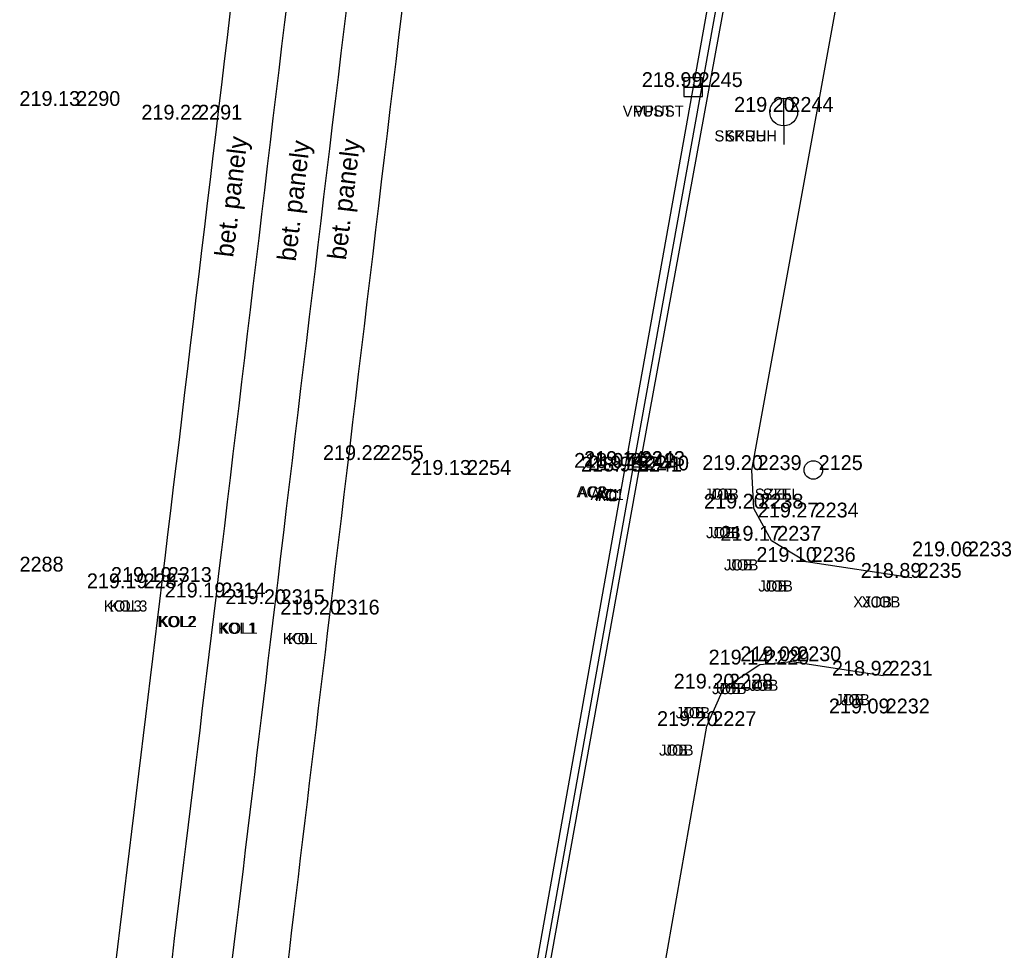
# Model space of a CAD drawing. Extents: x -471047 to -470889, y -1102859 to -1102000.
# Drawn here: x -470942.48 to -470915.72, y -1102237.69 to -1102212.58 of the extents above; entities that cross this region are included whole.
import ezdxf

# ---------------------------------------------------------------- set-up
doc = ezdxf.new("R2010")
doc.units = 0
for name, color, linetype in [('Vrstva 1', 7, 'Continuous'), ('Vrstva 22', 7, 'Continuous'), ('Vrstva 23', 7, 'Continuous'), ('Vrstva 25', 7, 'Continuous'), ('Vrstva 34', 7, 'Continuous'), ('Vrstva 35', 7, 'Continuous'), ('Vrstva 36', 7, 'Continuous'), ('Vrstva 38', 7, 'Continuous'), ('Vrstva 5', 7, 'Continuous'), ('Vrstva 7', 7, 'Continuous'), ('Vrstva 8', 7, 'Continuous')]:
    doc.layers.add(name, color=color, linetype=linetype)

msp = doc.modelspace()

# ---------------------------------------------------------------- linework, layer by layer
at = {"layer": 'Vrstva 1'}
for points in [[(-471040.344, -1102858.385), (-471031.676, -1102846.187), (-471026.357, -1102838.629), (-471023.212, -1102833.975), (-471019.21, -1102827.465), (-471016.861, -1102823.272), (-471013.099, -1102815.912), (-471010.824, -1102810.955), (-471007.329, -1102802.292), (-471005.34, -1102796.515), (-471002.842, -1102787.838), (-471001.3, -1102780.997), (-471000.19, -1102774.713), (-470999.247, -1102768.204), (-470998.794, -1102764.784), (-470997.199, -1102751.812), (-470994.899, -1102732.807), (-470992.551, -1102713.262), (-470990.326, -1102694.887), (-470988.122, -1102676.57), (-470985.812, -1102657.305), (-470983.537, -1102638.407), (-470981.386, -1102620.622), (-470979.843, -1102608.014), (-470976.377, -1102579.253), (-470972.945, -1102550.69), (-470970.475, -1102530.206), (-470967.905, -1102508.801), (-470965.053, -1102485.131), (-470962.734, -1102465.9), (-470960.173, -1102444.812), (-470957.795, -1102425.103), (-470954.965, -1102401.839), (-470953.834, -1102392.574), (-470952.33, -1102379.985), (-470950.744, -1102366.853), (-470948.978, -1102352.106), (-470947.037, -1102335.844), (-470944.949, -1102318.462), (-470944.013, -1102310.745), (-470942.39, -1102297.267), (-470939.519, -1102273.45), (-470937.593, -1102257.43), (-470936.064, -1102244.81), (-470934.114, -1102228.634), (-470931.621, -1102207.856), (-470929.536, -1102190.857), (-470926.572, -1102166.31), (-470924.91, -1102152.663), (-470923.413, -1102140.333), (-470921.923, -1102127.669), (-470921.155, -1102120.084), (-470920.446, -1102109.574), (-470919.912, -1102099.137), (-470919.63, -1102088.981), (-470919.523, -1102081.193), (-470919.563, -1102070.395), (-470919.714, -1102064.236), (-470920.134, -1102054.704), (-470920.462, -1102047.615), (-470920.599, -1102044.52), (-470920.743, -1102041.873), (-470921.125, -1102034.455), (-470921.774, -1102030.337), (-470922.418, -1102027.787), (-470923.734, -1102023.93), (-470924.872, -1102021.434), (-470926.752, -1102018.182), (-470927.953, -1102016.45), (-470929.616, -1102014.424), (-470932.252, -1102011.756), (-470935.111, -1102009.425), (-470938.391, -1102007.371), (-470942.651, -1102005.401)], [(-471041.328, -1102857.18), (-471032.144, -1102844.242), (-471027.583, -1102837.763), (-471024.388, -1102833.028), (-471020.451, -1102826.6), (-471018.089, -1102822.378), (-471014.542, -1102815.445), (-471012.233, -1102810.418), (-471009.247, -1102803.108), (-471006.795, -1102796.098), (-471004.315, -1102787.532), (-471002.782, -1102780.723), (-471001.674, -1102774.458), (-471000.75, -1102768.095), (-471000.28, -1102764.601), (-470998.692, -1102751.741), (-470996.378, -1102732.635), (-470994.028, -1102713.058), (-470991.808, -1102694.749), (-470989.616, -1102676.447), (-470987.284, -1102657.013), (-470985.031, -1102638.272), (-470982.87, -1102620.431), (-470981.334, -1102607.933), (-470977.881, -1102579.263), (-470974.429, -1102550.492), (-470971.964, -1102530.054), (-470969.391, -1102508.607), (-470966.54, -1102484.984), (-470964.231, -1102465.853), (-470961.679, -1102444.752), (-470959.304, -1102425.078), (-470956.455, -1102401.634), (-470955.339, -1102392.489), (-470953.812, -1102379.71), (-470952.249, -1102366.808), (-470950.479, -1102352.023), (-470948.536, -1102335.868), (-470946.426, -1102318.233), (-470945.493, -1102310.531), (-470943.864, -1102297.013), (-470940.984, -1102273.071), (-470939.078, -1102257.195), (-470937.559, -1102244.684), (-470935.592, -1102228.353), (-470933.101, -1102207.653), (-470931.011, -1102190.57), (-470928.046, -1102166.021), (-470926.409, -1102152.578), (-470924.898, -1102140.121), (-470923.427, -1102127.544), (-470922.647, -1102119.826), (-470921.919, -1102109.229), (-470921.42, -1102099.134), (-470921.127, -1102089.016), (-470921.023, -1102081.453), (-470921.061, -1102070.468), (-470921.209, -1102064.314), (-470921.666, -1102053.966), (-470922.156, -1102043.345), (-470922.299, -1102039.934), (-470922.637, -1102034.36), (-470923.091, -1102031.241), (-470923.847, -1102028.247), (-470925.083, -1102024.594), (-470926.222, -1102022.086), (-470928.04, -1102018.943), (-470929.138, -1102017.357), (-470930.929, -1102015.175), (-470933.062, -1102013.049), (-470936.379, -1102010.368), (-470939.169, -1102008.662), (-470942.899, -1102006.906), (-470945.661, -1102005.908)], [(-471043.557, -1102855.955), (-471035.129, -1102844.026), (-471029.872, -1102836.499), (-471026.577, -1102831.578), (-471022.675, -1102825.415), (-471020.123, -1102821.053), (-471016.667, -1102814.59), (-471014.208, -1102809.45), (-471011.177, -1102802.451), (-471008.55, -1102795.333), (-471006.082, -1102787.209), (-471004.464, -1102780.376), (-471003.265, -1102774.167), (-471002.327, -1102767.948), (-471001.636, -1102762.527), (-471000.297, -1102751.605), (-470997.959, -1102732.524), (-470995.602, -1102712.802), (-470993.412, -1102694.623), (-470991.21, -1102676.17), (-470988.891, -1102656.857), (-470986.625, -1102638.083), (-470984.455, -1102620.195), (-470982.936, -1102607.733), (-470979.497, -1102579.223), (-470976.023, -1102550.279), (-470973.554, -1102529.822), (-470970.991, -1102508.497), (-470968.146, -1102484.787), (-470965.835, -1102465.72), (-470963.284, -1102444.529), (-470960.91, -1102424.942), (-470958.043, -1102401.343), (-470956.946, -1102392.356), (-470955.396, -1102379.408), (-470953.851, -1102366.636), (-470952.049, -1102351.733), (-470950.124, -1102335.611), (-470948.034, -1102318.083), (-470947.094, -1102310.328), (-470945.421, -1102296.51), (-470942.58, -1102272.848), (-470940.675, -1102256.948), (-470939.176, -1102244.526), (-470937.187, -1102228.174), (-470934.708, -1102207.467), (-470932.621, -1102190.433), (-470929.634, -1102165.778), (-470928.004, -1102152.415), (-470926.45, -1102139.595), (-470925.003, -1102127.418), (-470924.249, -1102119.695), (-470923.515, -1102109.093), (-470923.018, -1102099.069), (-470922.711, -1102088.911), (-470922.643, -1102081.356), (-470922.797, -1102070.414), (-470923.018, -1102064.454), (-470923.52, -1102053.203), (-470923.823, -1102047.529), (-470924.123, -1102041.506), (-470924.462, -1102037.486), (-470924.934, -1102031.904), (-470925.664, -1102028.672), (-470926.771, -1102025.506), (-470927.959, -1102022.914), (-470929.674, -1102020.028), (-470930.76, -1102018.498), (-470932.447, -1102016.478), (-470935.215, -1102013.816), (-470937.644, -1102011.98), (-470940.381, -1102010.371), (-470943.968, -1102008.669), (-470947.145, -1102007.524), (-470950.874, -1102006.74)], [(-471044.756, -1102855.056), (-471036.376, -1102843.177), (-471031.167, -1102835.741), (-471027.859, -1102830.8), (-471023.934, -1102824.593), (-471021.43, -1102820.312), (-471018.011, -1102813.91), (-471015.536, -1102808.75), (-471012.578, -1102801.897), (-471009.95, -1102794.77), (-471007.561, -1102786.914), (-471005.936, -1102780.074), (-471004.727, -1102773.818), (-471003.828, -1102767.827), (-471003.121, -1102762.345), (-471001.787, -1102751.467), (-470999.446, -1102732.348), (-470997.073, -1102712.539), (-470994.902, -1102694.521), (-470992.696, -1102676.023), (-470990.376, -1102656.68), (-470988.131, -1102638.071), (-470985.947, -1102620.018), (-470984.417, -1102607.512), (-470980.993, -1102579.08), (-470977.514, -1102550.137), (-470975.048, -1102529.649), (-470972.488, -1102508.37), (-470969.618, -1102484.508), (-470967.34, -1102465.669), (-470964.767, -1102444.39), (-470962.402, -1102424.781), (-470959.534, -1102401.193), (-470958.432, -1102392.151), (-470956.883, -1102379.208), (-470955.335, -1102366.424), (-470953.535, -1102351.506), (-470951.606, -1102335.399), (-470949.519, -1102317.94), (-470948.575, -1102310.159), (-470946.889, -1102296.144), (-470944.056, -1102272.618), (-470942.139, -1102256.659), (-470940.657, -1102244.341), (-470938.638, -1102227.749), (-470936.19, -1102207.298), (-470934.102, -1102190.255), (-470931.124, -1102165.639), (-470929.492, -1102152.254), (-470927.915, -1102139.252), (-470926.46, -1102127.103), (-470925.74, -1102119.604), (-470925.012, -1102108.913), (-470924.523, -1102099.054), (-470924.217, -1102088.866), (-470924.148, -1102081.334), (-470924.301, -1102070.391), (-470924.518, -1102064.43), (-470924.97, -1102054.435), (-470925.588, -1102041.569), (-470925.963, -1102035.313), (-470926.405, -1102032.225), (-470927.078, -1102029.198), (-470928.123, -1102026.148), (-470929.318, -1102023.558), (-470930.84, -1102020.97), (-470931.868, -1102019.515), (-470933.443, -1102017.605), (-470936.26, -1102014.885), (-470938.429, -1102013.255), (-470941.213, -1102011.639), (-470944.847, -1102009.927), (-470947.723, -1102008.912), (-470951.444, -1102008.161), (-470954.511, -1102007.931), (-470957.895, -1102008.041)]]:
    msp.add_spline(points, degree=3, dxfattribs=at)
at = {"layer": 'Vrstva 23'}
msp.add_circle((-470921.065, -1102224.727), 0.25, dxfattribs=at)
at = {"layer": 'Vrstva 25'}
for p, q in [((-470924.56, -1102214.144), (-470924.56, -1102214.644)), ((-470924.06, -1102214.144), (-470924.56, -1102214.144)), ((-470924.06, -1102214.644), (-470924.06, -1102214.144)), ((-470924.56, -1102214.394), (-470924.06, -1102214.394)), ((-470924.56, -1102214.644), (-470924.06, -1102214.644)), ((-470921.864, -1102215.439), (-470921.864, -1102214.689)), ((-470921.864, -1102215.439), (-470921.864, -1102215.939))]:
    msp.add_line(p, q, dxfattribs=at)
msp.add_circle((-470921.864, -1102215.064), 0.375, dxfattribs=at)
at = {"layer": 'Vrstva 34'}
for p, q in [((-470924.31, -1102214.39), (-470924.31, -1102214.39)), ((-470941.11, -1102214.9), (-470941.11, -1102214.9)), ((-470937.82, -1102215.27), (-470937.82, -1102215.27)), ((-470921.86, -1102215.06), (-470921.86, -1102215.06)), ((-470932.92, -1102224.46), (-470932.92, -1102224.46)), ((-470925.87, -1102224.62), (-470925.87, -1102224.62)), ((-470930.56, -1102224.86), (-470930.56, -1102224.86)), ((-470926.14, -1102224.67), (-470926.14, -1102224.67)), ((-470925.95, -1102224.77), (-470925.95, -1102224.77)), ((-470925.76, -1102224.74), (-470925.76, -1102224.74)), ((-470922.72, -1102224.73), (-470922.72, -1102224.73)), ((-470921.07, -1102224.73), (-470921.07, -1102224.73)), ((-470922.67, -1102225.77), (-470922.67, -1102225.77)), ((-470921.18, -1102226.01), (-470921.18, -1102226.01)), ((-470922.19, -1102226.64), (-470922.19, -1102226.64)), ((-470921.26, -1102227.21), (-470921.26, -1102227.21)), ((-470917.04, -1102227.06), (-470917.04, -1102227.06)), ((-470938.64, -1102227.75), (-470938.64, -1102227.75)), ((-470918.4, -1102227.64), (-470918.4, -1102227.64)), ((-470939.29, -1102227.92), (-470939.29, -1102227.92)), ((-470937.19, -1102228.17), (-470937.19, -1102228.17)), ((-470935.59, -1102228.35), (-470935.59, -1102228.35)), ((-470934.11, -1102228.63), (-470934.11, -1102228.63)), ((-470922.51, -1102229.98), (-470922.51, -1102229.98)), ((-470921.65, -1102229.89), (-470921.65, -1102229.89)), ((-470919.18, -1102230.28), (-470919.18, -1102230.28)), ((-470923.49, -1102230.63), (-470923.49, -1102230.63)), ((-470919.26, -1102231.3), (-470919.26, -1102231.3)), ((-470923.94, -1102231.64), (-470923.94, -1102231.64))]:
    msp.add_line(p, q, dxfattribs=at)
at = {"layer": 'Vrstva 5'}
for p, q in [((-470926.14, -1102224.666), (-470923.084, -1102207.586)), ((-470929.245, -1102242.04), (-470926.14, -1102224.666))]:
    msp.add_line(p, q, dxfattribs=at)
at = {"layer": 'Vrstva 7'}
for p, q in [((-470925.762, -1102224.737), (-470922.651, -1102207.718)), ((-470928.905, -1102242.112), (-470925.762, -1102224.737))]:
    msp.add_line(p, q, dxfattribs=at)
at = {"layer": 'Vrstva 8'}
for p, q in [((-470925.95, -1102224.774), (-470922.83, -1102207.5)), ((-470922.725, -1102224.731), (-470919.801, -1102208.66)), ((-470929.047, -1102242.11), (-470925.95, -1102224.774)), ((-470922.673, -1102225.77), (-470922.725, -1102224.731)), ((-470922.194, -1102226.637), (-470922.673, -1102225.77)), ((-470921.257, -1102227.205), (-470922.194, -1102226.637)), ((-470918.403, -1102227.636), (-470921.257, -1102227.205)), ((-470923.494, -1102230.631), (-470922.505, -1102229.98)), ((-470922.505, -1102229.98), (-470921.649, -1102229.894)), ((-470921.649, -1102229.894), (-470919.181, -1102230.276)), ((-470923.943, -1102231.644), (-470923.494, -1102230.631)), ((-470925.675, -1102241.511), (-470923.943, -1102231.644))]:
    msp.add_line(p, q, dxfattribs=at)

# ---------------------------------------------------------------- texts
at = {"layer": 'Vrstva 22'}
for p in [(-470936.725, -1102219.003), (-470933.683, -1102219.076), (-470935.039, -1102219.112)]:
    msp.add_text('bet. panely', height=0.5, rotation=83.1381, dxfattribs=at).set_placement(p)
at = {"layer": 'Vrstva 35'}
for s, p in [('VPUST', (-470926.21, -1102215.19)), ('VPUST', (-470925.899, -1102215.19)), ('SKRUH', (-470923.735, -1102215.86)), ('SKRUH', (-470923.449, -1102215.86)), ('AC2', (-470927.456, -1102225.47)), ('AC2', (-470927.415, -1102225.47)), ('AC1', (-470927.077, -1102225.54)), ('AC1', (-470926.96, -1102225.54)), ('AC', (-470926.939, -1102225.57)), ('AC', (-470926.864, -1102225.57)), ('JOB', (-470924.009, -1102225.53)), ('JOB', (-470923.859, -1102225.53)), ('SZEL', (-470922.645, -1102225.53)), ('SZEL', (-470922.434, -1102225.53)), ('JOB', (-470923.959, -1102226.57)), ('JOB', (-470923.809, -1102226.57)), ('JOB', (-470923.479, -1102227.44)), ('JOB', (-470923.329, -1102227.44)), ('JOB', (-470922.549, -1102228.01)), ('JOB', (-470922.399, -1102228.01)), ('KOL3', (-470940.215, -1102228.55)), ('KOL3', (-470940.068, -1102228.55)), ('XJOB', (-470919.989, -1102228.44)), ('XJOB', (-470919.764, -1102228.44)), ('KOL2', (-470938.765, -1102228.97)), ('KOL2', (-470938.731, -1102228.97)), ('KOL1', (-470937.132, -1102229.15)), ('KOL1', (-470937.09, -1102229.15)), ('KOL', (-470935.385, -1102229.43)), ('KOL', (-470935.249, -1102229.43)), ('JOB', (-470923.799, -1102230.78)), ('JOB', (-470923.649, -1102230.78)), ('JOB', (-470922.939, -1102230.69)), ('JOB', (-470922.789, -1102230.69)), ('JOB', (-470920.469, -1102231.08)), ('JOB', (-470920.319, -1102231.08)), ('JOB', (-470924.779, -1102231.43)), ('JOB', (-470924.629, -1102231.43)), ('JOB', (-470925.229, -1102232.44)), ('JOB', (-470925.079, -1102232.44))]:
    msp.add_text(s, height=0.3, dxfattribs=at).set_placement(p)
at = {"layer": 'Vrstva 36'}
for s, p in [(' 2245', (-470924.31, -1102214.39)), (' 2290', (-470941.11, -1102214.9)), (' 2244', (-470921.86, -1102215.06)), (' 2291', (-470937.82, -1102215.27)), (' 2255', (-470932.92, -1102224.46)), (' 2242', (-470926.14, -1102224.67)), (' 2241', (-470925.95, -1102224.77)), (' 2243', (-470925.87, -1102224.62)), (' 2240', (-470925.76, -1102224.74)), (' 2239', (-470922.72, -1102224.73)), (' 2125', (-470921.07, -1102224.73)), (' 2254', (-470930.56, -1102224.86)), (' 2238', (-470922.67, -1102225.77)), (' 2234', (-470921.18, -1102226.01)), (' 2237', (-470922.19, -1102226.64)), (' 2233', (-470917.04, -1102227.06)), (' 2236', (-470921.26, -1102227.21)), (' 2288', (-470942.64, -1102227.47)), (' 2235', (-470918.4, -1102227.64)), (' 2287', (-470939.29, -1102227.92)), (' 2313', (-470938.64, -1102227.75)), (' 2314', (-470937.19, -1102228.17)), (' 2315', (-470935.59, -1102228.35)), (' 2316', (-470934.11, -1102228.63)), (' 2229', (-470922.51, -1102229.98)), (' 2230', (-470921.65, -1102229.89)), (' 2231', (-470919.18, -1102230.28)), (' 2228', (-470923.49, -1102230.63)), (' 2232', (-470919.26, -1102231.3)), (' 2227', (-470923.94, -1102231.64))]:
    msp.add_text(s, height=0.4, dxfattribs=at).set_placement(p)
at = {"layer": 'Vrstva 38'}
for s, p in [('218.99 ', (-470925.694, -1102214.39)), ('219.13 ', (-470942.493, -1102214.9)), ('219.20 ', (-470923.203, -1102215.06)), ('219.22 ', (-470939.201, -1102215.27)), ('219.22 ', (-470934.301, -1102224.46)), ('218.97 ', (-470927.523, -1102224.67)), ('218.98 ', (-470927.334, -1102224.77)), ('219.14 ', (-470927.252, -1102224.62)), ('219.15 ', (-470927.144, -1102224.74)), ('219.20 ', (-470924.063, -1102224.73)), ('219.13 ', (-470931.943, -1102224.86)), ('219.20 ', (-470924.013, -1102225.77)), ('219.27 ', (-470922.563, -1102226.01)), ('219.17 ', (-470923.573, -1102226.64)), ('219.06 ', (-470918.4, -1102227.06)), ('219.10 ', (-470922.603, -1102227.21)), ('218.89 ', (-470919.784, -1102227.64)), ('219.19 ', (-470940.674, -1102227.92)), ('219.19 ', (-470940.024, -1102227.75)), ('219.19 ', (-470938.574, -1102228.17)), ('219.20 ', (-470936.933, -1102228.35)), ('219.20 ', (-470935.453, -1102228.63)), ('219.14 ', (-470923.892, -1102229.98)), ('219.09 ', (-470923.034, -1102229.89)), ('218.92 ', (-470920.561, -1102230.28)), ('219.20 ', (-470924.833, -1102230.63)), ('219.09 ', (-470920.644, -1102231.3)), ('219.20 ', (-470925.283, -1102231.64))]:
    msp.add_text(s, height=0.4, dxfattribs=at).set_placement(p)

doc.saveas('drawing.dxf')
